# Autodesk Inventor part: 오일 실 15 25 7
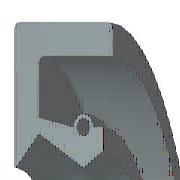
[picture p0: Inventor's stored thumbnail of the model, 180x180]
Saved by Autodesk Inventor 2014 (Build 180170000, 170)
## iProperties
Created: 2012-02
Part Number: 오일 실 15 25 7
Material: 고무
Description: 오일-실
Document SubType Name: Modeling
Standard: KS B 2804
Designer: mduedu
Standards Organization: KS
Language: ko-KR
Size Designation: D - 15 25 7
Categories: <MemberInstance><Categories><Category DisplayName="샤프트 부품" InternalName="7f7aeb1f-a693-4053-b835-cee3144e0d98" Mnemonic="SHFT"><Category DisplayName="실링" Intern
Density: 0.93 g/cm^3
Appearance: Rubber - Black - Version 1.1
IsCustomPart: 1
Author: mduedu
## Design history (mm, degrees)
revolve "본체" stored, may be unused: angle "d17" = 90 deg
revolve "스프링1" stored, may be unused: angle "d18" = 90 deg
body "Solid1"
sketch "스케치1"
  geometry: L1 (0, 12.5)-(7, 12.5); L2 (7, 10.75)-(1.75, 10.75); L3 (1.75, 9.25)-(4.9, 7.5); L4 (4.9, 7.5)-(0, 7.5); L5 (0, 0)-(9.586, 0) reference; L6 (4.9, 7.5)-(6.3, 8.375); L7 (0, 18)-(0, -3) reference; L8 (-1.941, 0)-(11.507, 0) reference; L9 (4.2, 9.6)-(1.75, 10.09); L10 (1.75, 10.09)-(1.75, 10.75); L11 (0, 12.5)-(0, 7.588); L12 (4.9, 7.5)-(0, 7.5); L13 (1.75, 9.25)-(0.152, 7.528); L14 (7, 12.5)-(7, 10.75); L15 (5.6, 9.6)-(6.3, 9.6); L16 (6.3, 9.6)-(6.3, 8.375); C1 r 0.455 at (4.9, 9.6); A1 r 0.7 centre (4.9, 9.6) between (5.6, 9.6) and (4.2, 9.6); A2 r 0.088 centre (0.088, 7.588) between (0, 7.588) and (0.152, 7.528); 1 further point
  constraints: 28 end point, 5 horizontal alignment, 5 point on line, 4 point on circle, 4 vertical alignment, 3 centre point, 3 tangent, 2 collinear, 2 horizontal, 2 perpendicular, 1 coincident, 1 parallel
  dimensions: "d0" = 25 diameter of L1 L5 (= SD2); "d1" = 1.75 distance of L1.end L2.start (= SD); "d2" = 0.91 diameter of C1 (= SPDI); "d3" = 1.4 diameter of A1 (= SPDA); "d4" = 15 diameter of L3.end L5 (= NND); "d5" = 18.5 diameter of L3.start L5 (= TKDM); "d7" = 20.18 diameter of L9.end L5 (= TKDM + 0.24 x SWDT); "d8" = 1.75 distance between parallel lines of L11 L10 (= SD); "d9" = 4.9 distance from line of L11 C1.centre (= SPDST); "d10" = 19.2 diameter of C1.centre L5 (= HLDM); "d11" = 0.0875 radius of A2 (= 0.25 x LAB); "d12" = 6.3 distance between parallel lines of L11 L16 (= SDI); "d13" = 16.75 diameter of L6.end L5 (= ABDM); "d14" = 7 distance from line of L11 L1.end (= SWDT)
fillet "모깎기1" dims "d6" = 0.3 (= RR)
other parameters: "SD2" = 25 [user parameter; used in 1 equation term], "SWDT" = 7 [user parameter; used in 2 equation terms], "RR" = 0.3 [user parameter; used in 1 equation term], "SD" = 1.75 [user parameter; used in 2 equation terms], "NND" = 15 [user parameter; used in 1 equation term], "SPDA" = 1.4 [user parameter; used in 1 equation term], "SPDI" = 0.91 [user parameter; used in 1 equation term], "TKDM" = 18.5 [user parameter; used in 2 equation terms], "HLDM" = 19.2 [user parameter; used in 1 equation term], "ABDM" = 16.75 [user parameter; used in 1 equation term], "SDI" = 6.3 [user parameter; used in 1 equation term], "SPDST" = 4.9 [user parameter; used in 1 equation term], "LAB" = 0.35 [user parameter; used in 1 equation term], "d15" = 0, "d16" = 0, "d19" = 0
